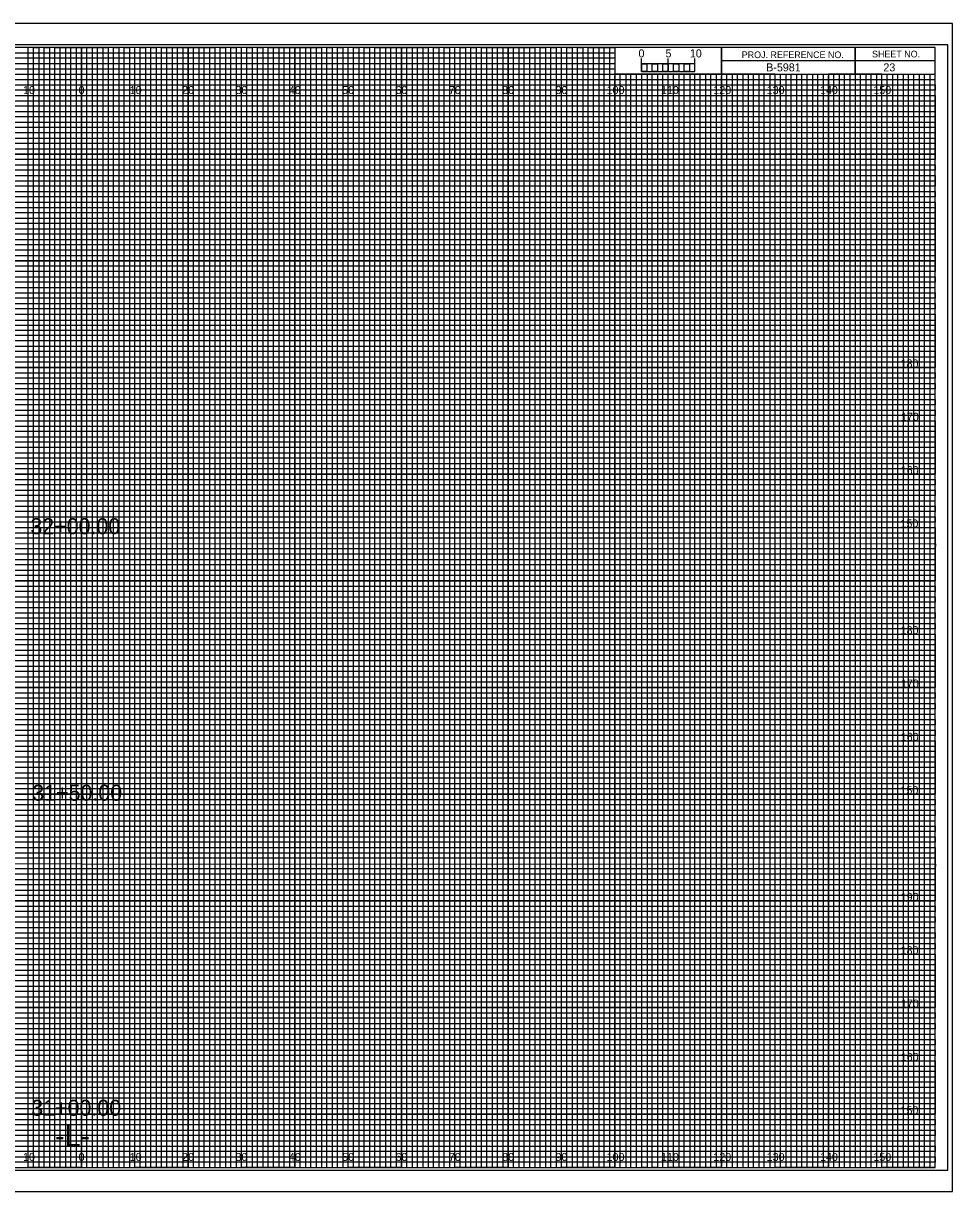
# Model space of a CAD drawing. Extents: x -13 to 323, y -5 to 4174.
# Drawn here: x 149.1 to 323.3, y 3735.5 to 3954.5 of the extents above; entities that cross this region are included whole.
import ezdxf

# ---------------------------------------------------------------- set-up
doc = ezdxf.new("R2010")
doc.units = 0
for name, color, linetype in [('Exist Cross Section Cell', 7, 'Continuous'), ('Exist XS Center Line Elevation Label', 7, 'Continuous'), ('Exist XS Ground Line', 7, 'Continuous'), ('Prop CMT Concrete Structures', 7, 'Continuous'), ('Prop CMT Guardrail Graphics', 7, 'Continuous'), ('Prop CMT Pvmt Course 1', 7, 'Continuous'), ('Prop CMT Pvmt Course 2', 7, 'Continuous'), ('Prop CMT Pvmt Course 3', 7, 'Continuous'), ('Prop CMT Pvmt Surface', 7, 'Continuous'), ('Prop CMT Shld Paved Course 1', 7, 'Continuous'), ('Prop CMT Shld Paved Course 2', 7, 'Continuous'), ('Prop CMT Shld Paved Course 3', 7, 'Continuous'), ('Prop CMT Subgrade Earthwork', 7, 'Continuous'), ('Prop XS Ditch Standard Text', 7, 'Continuous'), ('Prop XS SE Text', 7, 'Continuous'), ('Prop XS Side Slope Text', 7, 'Continuous'), ('Scratch_Level_0', 7, 'Continuous')]:
    doc.layers.add(name, color=color, linetype=linetype)

msp = doc.modelspace()

# ---------------------------------------------------------------- linework, layer by layer
at = {"layer": 'Exist XS Center Line Elevation Label'}
for points in [[(145, 3740), (155, 3740), (155, 3950), (165, 3950), (165, 3740), (175, 3740), (175, 3950), (185, 3950), (185, 3740), (195, 3740), (195, 3950), (205, 3950), (205, 3740), (215, 3740), (215, 3950), (225, 3950), (225, 3740), (235, 3740), (235, 3950), (245, 3950), (245, 3740), (255, 3740), (255, 3950), (259.93, 3950), (260, 3950), (260, 3945), (264.99, 3945), (264.99, 3740), (275, 3740), (275, 3945), (285, 3945), (285, 3740), (295, 3740), (295, 3945), (305, 3945), (305, 3740), (315, 3740), (315, 3945)], [(0, 3945), (275, 3945)], [(0, 3925), (320, 3925), (320, 3935), (0, 3935)], [(0, 3905), (320, 3905), (320, 3915), (0, 3915)], [(0, 3885), (320, 3885), (320, 3895), (0, 3895)], [(0, 3865), (320, 3865), (320, 3875), (0, 3875)], [(0, 3845), (320, 3845), (320, 3855), (0, 3855)], [(0, 3825), (320, 3825), (320, 3835), (0, 3835)], [(0, 3805), (320, 3805), (320, 3815), (0, 3815)], [(0, 3785), (320, 3785), (320, 3795), (0, 3795)], [(0, 3765), (320, 3765), (320, 3775), (0, 3775)], [(0, 3745), (320, 3745), (320, 3755), (0, 3755)]]:
    msp.add_lwpolyline(points, dxfattribs=at)
at = {"layer": 'Exist XS Ground Line'}
for p, q in [((150, 3950), (140, 3950)), ((150, 3740), (150, 3950)), ((170, 3950), (160, 3950)), ((160, 3950), (160, 3740)), ((170, 3740), (170, 3950)), ((190, 3950), (180, 3950)), ((180, 3950), (180, 3740)), ((190, 3740), (190, 3950)), ((210, 3950), (200, 3950)), ((200, 3950), (200, 3740)), ((210, 3740), (210, 3950)), ((230, 3950), (220, 3950)), ((220, 3950), (220, 3740)), ((230, 3740), (230, 3950)), ((250, 3950), (240, 3950)), ((240, 3950), (240, 3740)), ((250, 3740), (250, 3950)), ((260, 3950), (260, 3740)), ((270, 3740), (270, 3945)), ((290, 3945), (280, 3945)), ((280, 3945), (280, 3740)), ((290, 3740), (290, 3945)), ((310, 3945), (300, 3945)), ((300, 3945), (300, 3740)), ((310, 3740), (310, 3945)), ((160, 3740), (150, 3740)), ((180, 3740), (170, 3740)), ((200, 3740), (190, 3740)), ((220, 3740), (210, 3740)), ((240, 3740), (230, 3740)), ((260, 3740), (250, 3740)), ((280, 3740), (270, 3740)), ((300, 3740), (290, 3740)), ((320, 3740), (310, 3740)), ((320, 3740), (320, 3740))]:
    msp.add_line(p, q, dxfattribs=at)
for points in [[(0, 3940), (320, 3940), (320, 3930), (0, 3930)], [(0, 3920), (320, 3920), (320, 3910), (0, 3910)], [(0, 3900), (320, 3900), (320, 3890), (0, 3890)], [(0, 3880), (320, 3880), (320, 3870), (0, 3870)], [(0, 3860), (320, 3860), (320, 3850), (0, 3850)], [(0, 3840), (320, 3840), (320, 3830), (0, 3830)], [(0, 3820), (320, 3820), (320, 3810), (0, 3810)], [(0, 3800), (320, 3800), (320, 3790), (0, 3790)], [(0, 3780), (320, 3780), (320, 3770), (0, 3770)], [(0, 3760), (320, 3760), (320, 3750), (0, 3750)]]:
    msp.add_lwpolyline(points, dxfattribs=at)
at = {"layer": 'Prop CMT Pvmt Course 1'}
for p, q in [((323.3, 3954.5), (-13.4, 3954.5)), ((-13.4, 3735.5), (323.3, 3735.5))]:
    msp.add_line(p, q, dxfattribs=at)
at = {"layer": 'Prop CMT Pvmt Course 2'}
msp.add_lwpolyline([(-13.4, 3735.5), (323.3, 3735.5), (323.3, 3954.5), (-13.4, 3954.5)], close=True, dxfattribs=at)
at = {"layer": 'Prop CMT Pvmt Course 3'}
msp.add_lwpolyline([(-10.8, 3739.5), (322.4, 3739.5), (322.4, 3950.5), (-10.8, 3950.5)], close=True, dxfattribs=at)
at = {"layer": 'Prop CMT Shld Paved Course 1'}
for p, q in [((305, 3950), (305, 3945)), ((305, 3945), (305, 3950)), ((280, 3947.5), (280, 3945)), ((320, 3947.49), (280, 3947.49)), ((280, 3945), (320, 3945))]:
    msp.add_line(p, q, dxfattribs=at)
for points in [[(320, 3950), (0, 3950), (0, 3740), (320, 3740)], [(280, 3950), (260, 3950), (260, 3945.03), (280, 3945.03)], [(320, 3950), (280, 3950), (280, 3945), (320, 3945)]]:
    msp.add_lwpolyline(points, close=True, dxfattribs=at)
at = {"layer": 'Prop CMT Shld Paved Course 2'}
for p, q in [((267, 3945), (266.01, 3945)), ((266.01, 3945), (266.01, 3740)), ((267, 3740), (267, 3945)), ((269, 3945), (268, 3945)), ((268, 3945), (268, 3740)), ((269, 3740), (269, 3945)), ((266.01, 3740), (265, 3740)), ((268, 3740), (267, 3740))]:
    msp.add_line(p, q, dxfattribs=at)
for points in [[(150, 3740), (151, 3740), (151, 3950), (152, 3950), (152, 3740)], [(152, 3740), (153, 3740), (153, 3950), (154, 3950), (154, 3740)], [(155, 3740), (156, 3740), (156, 3950), (157, 3950), (157, 3740)], [(157, 3740), (158, 3740), (158, 3950), (159, 3950), (159, 3740)], [(160, 3740), (161, 3740), (161, 3950), (162, 3950), (162, 3740)], [(162, 3740), (163, 3740), (163, 3950), (164, 3950), (164, 3740)], [(165, 3740), (166, 3740), (166, 3950), (167, 3950), (167, 3740)], [(167, 3740), (168, 3740), (168, 3950), (169, 3950), (169, 3740)], [(170, 3740), (171, 3740), (171, 3950), (172, 3950), (172, 3740)], [(172, 3740), (173, 3740), (173, 3950), (174, 3950), (174, 3740)], [(175, 3740), (176, 3740), (176, 3950), (177, 3950), (177, 3740)], [(177, 3740), (178, 3740), (178, 3950), (179, 3950), (179, 3740)], [(180, 3740), (181, 3740), (181, 3950), (182, 3950), (182, 3740)], [(182, 3740), (183, 3740), (183, 3950), (184, 3950), (184, 3740)], [(185, 3740), (186, 3740), (186, 3950), (187, 3950), (187, 3740)], [(187, 3740), (188, 3740), (188, 3950), (189, 3950), (189, 3740)], [(190, 3740), (191, 3740), (191, 3950), (192, 3950), (192, 3740)], [(192, 3740), (193, 3740), (193, 3950), (194, 3950), (194, 3740)], [(195, 3740), (196, 3740), (196, 3950), (197, 3950), (197, 3740)], [(197, 3740), (198, 3740), (198, 3950), (199, 3950), (199, 3740)], [(200, 3740), (201, 3740), (201, 3950), (202, 3950), (202, 3740)], [(202, 3740), (203, 3740), (203, 3950), (204, 3950), (204, 3740)], [(205, 3740), (206, 3740), (206, 3950), (207, 3950), (207, 3740)], [(207, 3740), (208, 3740), (208, 3950), (209, 3950), (209, 3740)], [(210, 3740), (211, 3740), (211, 3950), (212, 3950), (212, 3740)], [(212, 3740), (213, 3740), (213, 3950), (214, 3950), (214, 3740)], [(215, 3740), (216, 3740), (216, 3950), (217, 3950), (217, 3740)], [(217, 3740), (218, 3740), (218, 3950), (219, 3950), (219, 3740)], [(220, 3740), (221, 3740), (221, 3950), (222, 3950), (222, 3740)], [(222, 3740), (223, 3740), (223, 3950), (224, 3950), (224, 3740)], [(225, 3740), (226, 3740), (226, 3950), (227, 3950), (227, 3740)], [(227, 3740), (228, 3740), (228, 3950), (229, 3950), (229, 3740)], [(230, 3740), (231, 3740), (231, 3950), (232, 3950), (232, 3740)], [(232, 3740), (233, 3740), (233, 3950), (234, 3950), (234, 3740)], [(235, 3740), (236, 3740), (236, 3950), (237, 3950), (237, 3740)], [(237, 3740), (238, 3740), (238, 3950), (239, 3950), (239, 3740)], [(240, 3740), (241, 3740), (241, 3950), (242, 3950), (242, 3740)], [(242, 3740), (243, 3740), (243, 3950), (244, 3950), (244, 3740)], [(245, 3740), (246, 3740), (246, 3950), (247, 3950), (247, 3740)], [(247, 3740), (248, 3740), (248, 3950), (249, 3950), (249, 3740)], [(250, 3740), (251, 3740), (251, 3950), (252, 3950), (252, 3740)], [(252, 3740), (253, 3740), (253, 3950), (254, 3950), (254, 3740)], [(255, 3740), (256, 3740), (256, 3950), (257, 3950), (257, 3740)], [(257, 3740), (258, 3740), (258, 3950), (259, 3950), (259, 3740)], [(260, 3740), (261, 3740), (261, 3945), (262.02, 3945), (262.02, 3740)], [(262, 3740), (263, 3740), (263, 3945), (263.99, 3945), (263.99, 3740)], [(270, 3740), (270.98, 3740), (270.98, 3945), (272, 3945), (272, 3740)], [(272, 3740), (273, 3740), (273, 3945), (274.05, 3945), (274.05, 3740)], [(275, 3740), (276, 3740), (276, 3945), (277, 3945), (277, 3740)], [(277, 3740), (278, 3740), (278, 3945), (279, 3945), (279, 3740)], [(280, 3740), (281, 3740), (281, 3945), (282, 3945), (282, 3740)], [(282, 3740), (283, 3740), (283, 3945), (284, 3945), (284, 3740)], [(285, 3740), (286, 3740), (286, 3945), (287, 3945), (287, 3740)], [(287, 3740), (288, 3740), (288, 3945), (289, 3945), (289, 3740)], [(290, 3740), (291, 3740), (291, 3945), (292, 3945), (292, 3740)], [(292, 3740), (293, 3740), (293, 3945), (294, 3945), (294, 3740)], [(295, 3740), (296, 3740), (296, 3945), (297, 3945), (297, 3740)], [(297, 3740), (298, 3740), (298, 3945), (299, 3945), (299, 3740)], [(300, 3740), (301, 3740), (301, 3945), (302, 3945), (302, 3740)], [(302, 3740), (303, 3740), (303, 3945), (304, 3945), (304, 3740)], [(305, 3740), (306, 3740), (306, 3945), (307, 3945), (307, 3740)], [(307, 3740), (308, 3740), (308, 3945), (309, 3945), (309, 3740)], [(310, 3740), (311, 3740), (311, 3945), (312, 3945), (312, 3740)], [(312, 3740), (313, 3740), (313, 3945), (314, 3945), (314, 3740)], [(315, 3740), (316, 3740), (316, 3945), (317, 3945), (317, 3740)], [(317, 3740), (318, 3740), (318, 3945), (319, 3945), (319, 3740)]]:
    msp.add_lwpolyline(points, dxfattribs=at)
at = {"layer": 'Prop CMT Shld Paved Course 3'}
for p, q in [((265, 3945.49), (265, 3947.9)), ((265, 3946.9), (265, 3947.9)), ((270, 3945.49), (270, 3947.9)), ((275, 3945.49), (275, 3947.9)), ((275, 3946.9), (275, 3947.9))]:
    msp.add_line(p, q, dxfattribs=at)
for points in [[(275, 3946.9), (265, 3946.9), (265, 3945.49), (275, 3945.49)], [(265, 3946.9), (266, 3946.9), (266, 3945.49), (265, 3945.49)], [(267, 3946.9), (268, 3946.9), (268, 3945.49), (267, 3945.49)], [(269, 3946.9), (270, 3946.9), (270, 3945.49), (269, 3945.49)], [(271, 3946.9), (272, 3946.9), (272, 3945.49), (271, 3945.49)], [(273, 3946.9), (274, 3946.9), (274, 3945.49), (273, 3945.49)]]:
    msp.add_lwpolyline(points, close=True, dxfattribs=at)
at = {"layer": 'Prop CMT Subgrade Earthwork'}
for p, q in [((150, 3740), (150, 3950)), ((160, 3740), (160, 3950)), ((170, 3740), (170, 3950)), ((180, 3740), (180, 3950)), ((190, 3740), (190, 3950)), ((200, 3740), (200, 3950)), ((210, 3740), (210, 3950)), ((220, 3740), (220, 3950)), ((230, 3740), (230, 3950)), ((240, 3740), (240, 3950)), ((250, 3740), (250, 3950)), ((260, 3740), (260, 3944.69)), ((270, 3740), (270, 3944.69)), ((280, 3740), (280, 3944.69)), ((290, 3740), (290, 3944.69)), ((300, 3740), (300, 3944.69)), ((310, 3740), (310, 3944.69)), ((0, 3940), (320, 3940)), ((0, 3930), (320, 3930)), ((0, 3920), (320, 3920)), ((0, 3910), (320, 3910)), ((0, 3900), (320, 3900)), ((0, 3890), (320, 3890)), ((0, 3880), (320, 3880)), ((0, 3870), (320, 3870)), ((0, 3860), (320, 3860)), ((0, 3850), (320, 3850)), ((0, 3840), (320, 3840)), ((0, 3830), (320, 3830)), ((0, 3820), (320, 3820)), ((0, 3810), (320, 3810)), ((0, 3800), (320, 3800)), ((0, 3790), (320, 3790)), ((0, 3780), (320, 3780)), ((0, 3770), (320, 3770)), ((0, 3760), (320, 3760)), ((0, 3750), (320, 3750))]:
    msp.add_line(p, q, dxfattribs=at)
at = {"layer": 'Scratch_Level_0'}
for p, q in [((0, 3949), (260, 3949)), ((260, 3949), (260, 3947.98)), ((260, 3947.98), (0, 3947.98)), ((0, 3947), (260, 3947)), ((260, 3947), (260, 3945.89)), ((260, 3945.89), (0, 3945.89)), ((0, 3944), (320, 3944))]:
    msp.add_line(p, q, dxfattribs=at)
for points in [[(0, 3943), (270, 3943), (320, 3943), (320, 3942), (0, 3942)], [(0, 3941), (320, 3941), (320, 3939), (0, 3939)], [(0, 3938), (320, 3938), (320, 3937), (0, 3936.98)], [(0, 3936), (320, 3936), (320, 3934), (0, 3934)], [(0, 3933), (320, 3933), (320, 3932), (0, 3932)], [(0, 3931), (320, 3931), (320, 3929), (0, 3929)], [(0, 3928), (320, 3928), (320, 3927), (0, 3927)], [(0, 3926), (320, 3926), (320, 3924), (0, 3924)], [(0, 3923), (320, 3923), (320, 3922), (0, 3922)], [(0, 3921), (320, 3921), (320, 3919), (0, 3919)], [(0, 3918), (320, 3918), (320, 3917), (0, 3917)], [(0, 3916), (320, 3916), (320, 3913.95), (320, 3913), (320, 3912), (0, 3912)], [(0, 3914), (320, 3914), (320, 3913), (0, 3913)], [(0, 3911), (320, 3911), (320, 3909), (0, 3909.03)], [(0, 3909.03), (320, 3909), (320, 3908), (0, 3908)], [(0, 3907), (320, 3907), (320, 3906), (0, 3906)], [(0, 3904), (320, 3904), (320, 3903), (0, 3903)], [(0, 3902), (320, 3902), (320, 3901), (0, 3901)], [(-0.07, 3898.89), (320, 3898.89), (320, 3897.88), (-0.07, 3897.88)], [(0, 3897), (320, 3897), (320, 3896), (0, 3896)], [(0, 3894), (320, 3894), (320, 3893), (0, 3893)], [(0, 3892), (320, 3892), (320, 3891), (0, 3891)], [(0, 3889), (320, 3889), (320, 3888), (0, 3888)], [(0, 3887), (320, 3887), (320, 3886), (0, 3886)], [(0, 3884), (320, 3884), (320, 3883), (0, 3883)], [(0, 3882), (320, 3882), (320, 3881), (0, 3881)], [(0, 3879), (320, 3879), (319.99, 3877.98), (0, 3878)], [(0, 3877), (320, 3877), (320, 3876), (0, 3876)], [(0, 3874), (320, 3874), (320, 3873), (0, 3873)], [(0, 3872), (320, 3872), (320, 3871), (0, 3871)], [(0, 3869), (320, 3869), (320, 3868), (0, 3868)], [(0, 3867), (320, 3867), (320, 3866), (0, 3866)], [(0, 3864), (320, 3864), (320, 3863), (0, 3863)], [(0, 3862), (320, 3862), (320, 3861), (0, 3861)], [(0, 3859), (320, 3859), (320, 3858), (0, 3858)], [(0, 3856.99), (320.07, 3856.91), (320, 3856), (0, 3856)], [(0, 3854), (320, 3854), (320, 3853), (0, 3853)], [(0, 3852), (320, 3852), (320, 3851), (0, 3851)], [(0, 3849), (320, 3849), (320, 3848), (0, 3848)], [(0, 3847), (320, 3847), (320, 3846), (0, 3846)], [(0, 3844), (320, 3844), (320, 3843), (0, 3843)], [(0, 3842), (320, 3842), (320, 3841), (0, 3841)], [(0, 3839), (320, 3839), (320, 3838), (0, 3838)], [(0, 3837), (320, 3837), (320, 3836), (0, 3836)], [(0, 3834), (320, 3834), (320, 3833), (0, 3833)], [(0, 3832), (320, 3832), (320, 3831), (0, 3831)], [(0, 3829), (320, 3829), (320, 3828), (0, 3828)], [(0, 3827), (320, 3827), (320, 3826), (0, 3826)], [(0, 3824), (320, 3824), (320, 3823), (0, 3823)], [(0, 3822), (320, 3822), (320, 3821), (0, 3821)], [(0, 3819), (320, 3819), (319.99, 3817.98), (0, 3818)], [(0, 3817), (320, 3817), (320, 3816), (0, 3816)], [(0, 3814), (320, 3814), (320, 3813), (0, 3813)], [(0, 3812), (320, 3812), (320, 3811), (0, 3811)], [(0, 3809), (320, 3809), (320, 3808), (0, 3808)], [(0, 3807), (320, 3807), (320, 3806), (0, 3806)], [(0, 3804), (320, 3804), (320, 3803), (0, 3803)], [(0, 3802), (320, 3802), (320, 3801), (0, 3801)], [(0, 3799), (320, 3799), (320, 3798), (0, 3798)], [(0, 3796.99), (320.07, 3796.91), (320, 3796), (0, 3796)], [(0, 3794), (320, 3794), (320, 3793), (0, 3793)], [(0, 3792), (320, 3792), (320, 3791), (0, 3791)], [(0, 3789), (320, 3789), (320, 3788), (0, 3788)], [(0, 3787), (320, 3787), (320, 3786), (0, 3786)], [(0, 3784), (320, 3784), (320, 3783), (0, 3783)], [(0, 3782), (320, 3782), (320, 3781), (0, 3781)], [(0, 3779), (320, 3779), (320, 3778), (0, 3778)], [(0, 3777), (320, 3777), (320, 3776), (0, 3776)], [(0, 3774), (320, 3774), (320, 3773), (0, 3773)], [(0, 3772), (320, 3772), (320, 3771), (0, 3771)], [(0, 3769), (320, 3769), (320, 3768), (0, 3768)], [(0, 3767), (320, 3767), (320, 3766), (0, 3766)], [(0, 3764), (320, 3764), (320, 3763), (0, 3763)], [(0, 3762), (320, 3762), (320, 3761), (0, 3761)], [(0, 3759), (320, 3759), (320, 3758), (0, 3758)], [(0, 3757), (320, 3757), (320, 3756), (0, 3756)], [(0, 3754), (320, 3754), (320, 3753), (0, 3753)], [(0, 3752), (320, 3752), (320, 3751), (0, 3751)], [(0, 3749), (320, 3749), (320, 3748), (0, 3748)], [(0, 3747), (320, 3747), (320, 3746), (0, 3746)], [(0, 3744), (320, 3744), (320, 3743), (0, 3743)], [(0, 3742), (320, 3742), (320, 3741), (0, 3741)]]:
    msp.add_lwpolyline(points, dxfattribs=at)

# ---------------------------------------------------------------- texts
at = {"layer": 'Exist Cross Section Cell'}
for s, p in [('10', (149.04, 3941.25)), ('0', (159.45, 3941.25)), ('0', (159.45, 3941.25)), ('10', (169.04, 3941.25)), ('20', (178.86, 3941.25)), ('30', (188.86, 3941.25)), ('40', (198.86, 3941.25)), ('50', (208.86, 3941.25)), ('60', (218.86, 3941.25)), ('70', (228.86, 3941.25)), ('80', (238.86, 3941.25)), ('90', (248.86, 3941.25)), ('100', (258.44, 3941.25)), ('110', (268.62, 3941.25)), ('120', (278.44, 3941.25)), ('130', (288.44, 3941.25)), ('140', (298.44, 3941.25)), ('150', (308.44, 3941.25)), ('10', (149.04, 3741.25)), ('0', (159.45, 3741.25)), ('0', (159.45, 3741.25)), ('10', (169.04, 3741.25)), ('20', (178.86, 3741.25)), ('30', (188.86, 3741.25)), ('40', (198.86, 3741.25)), ('50', (208.86, 3741.25)), ('60', (218.86, 3741.25)), ('70', (228.86, 3741.25)), ('80', (238.86, 3741.25)), ('90', (248.86, 3741.25)), ('100', (258.44, 3741.25)), ('110', (268.62, 3741.25)), ('120', (278.44, 3741.25)), ('130', (288.44, 3741.25)), ('140', (298.44, 3741.25)), ('150', (308.44, 3741.25))]:
    msp.add_text(s, height=1.5, dxfattribs=at).set_placement(p)
at = {"layer": 'Prop CMT Concrete Structures'}
for s, p in [('32+00.00', (150.41, 3858.74)), ('31+50.00', (150.77, 3808.78)), ('31+00.00', (150.58, 3749.72))]:
    msp.add_text(s, height=3, dxfattribs=at).set_placement(p)
at = {"layer": 'Prop CMT Guardrail Graphics'}
for s, p in [('180', (313.55, 3890)), ('170', (313.61, 3880)), ('160', (313.57, 3870)), ('150', (313.52, 3860)), ('180', (313.55, 3840)), ('170', (313.61, 3830)), ('160', (313.57, 3820)), ('150', (313.52, 3810)), ('190', (313.57, 3790)), ('180', (313.55, 3780)), ('170', (313.61, 3770)), ('160', (313.57, 3760)), ('150', (313.52, 3750))]:
    msp.add_text(s, height=1.5, dxfattribs=at).set_placement(p)
at = {"layer": 'Prop CMT Pvmt Surface'}
for s, p in [('5', (269.47, 3948.12)), ('10', (274.04, 3948.12))]:
    msp.add_text(s, height=1.5, dxfattribs=at).set_placement(p)
at = {"layer": 'Prop CMT Shld Paved Course 1'}
for s, p in [('PROJ. REFERENCE NO.', (283.77, 3947.99)), ('SHEET NO.', (308.19, 3948.12))]:
    msp.add_text(s, height=1.25, dxfattribs=at).set_placement(p)
at = {"layer": 'Prop CMT Shld Paved Course 3'}
msp.add_text('0', height=1.5, dxfattribs=at).set_placement((264.41, 3948.12))
at = {"layer": 'Prop XS Ditch Standard Text'}
msp.add_text('-L-', height=4, dxfattribs=at).set_placement((155.06, 3744))
at = {"layer": 'Prop XS SE Text'}
msp.add_text(' B-5981', height=1.5, dxfattribs=at).set_placement((287.79, 3945.5))
at = {"layer": 'Prop XS Side Slope Text'}
msp.add_text('23', height=1.5, dxfattribs=at).set_placement((310.32, 3945.5))

doc.saveas('drawing.dxf')
